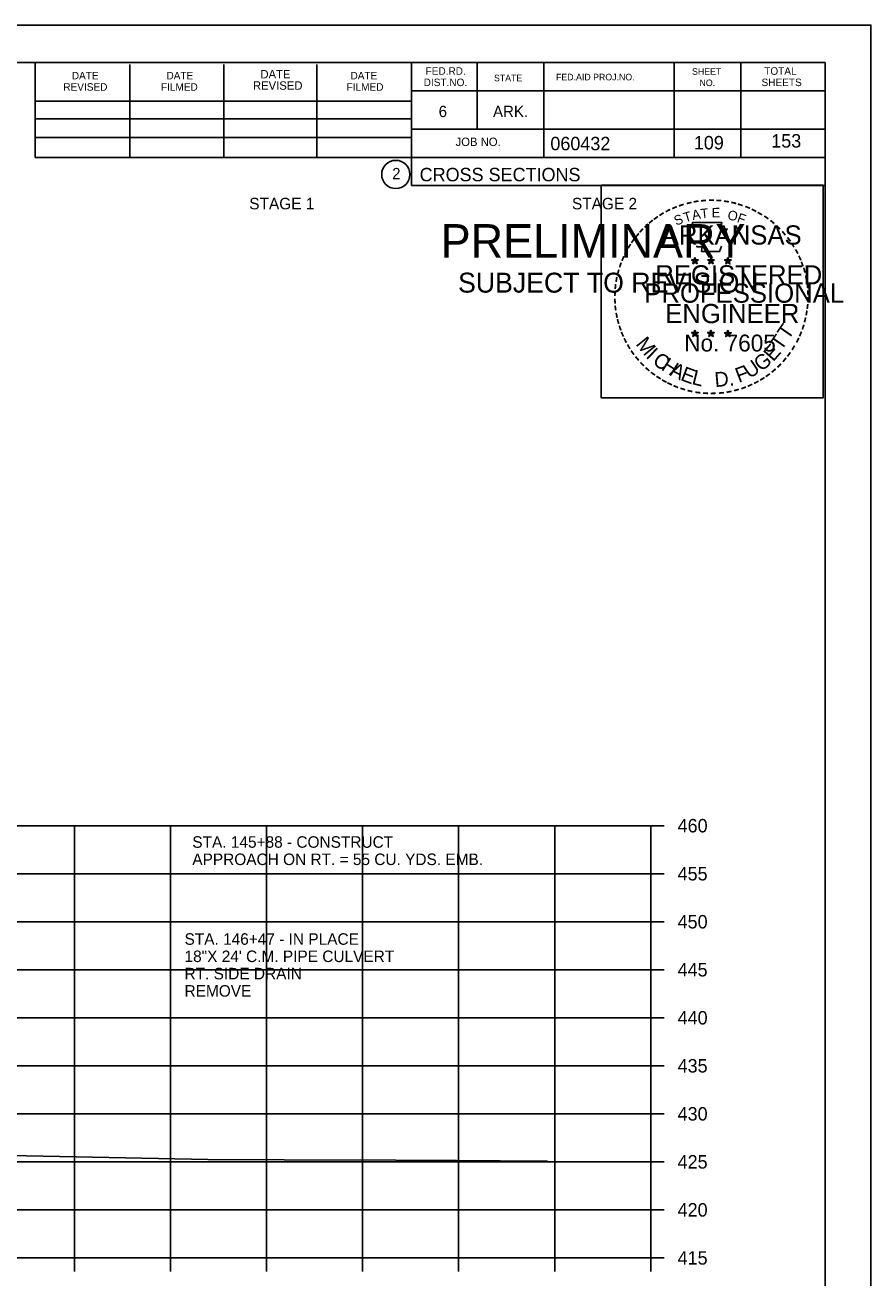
# Model space of a CAD drawing. Extents: x 1538688 to 1540766, y 656250 to 671912.
# Drawn here: x 1538933 to 1539021.1, y 663674.3 to 663804.7 of the extents above; entities that cross this region are included whole.
import ezdxf

# ---------------------------------------------------------------- set-up
doc = ezdxf.new("R2010")
doc.units = 0
for name, color, linetype in [('18', 7, 'Continuous'), ('22', 7, 'Continuous'), ('26', 7, 'Continuous'), ('7', 7, 'Continuous'), ('8', 7, 'Continuous'), ('9', 7, 'Continuous'), ('Borings', 7, 'Continuous'), ('Default', 7, 'Continuous'), ('Horizontal Alignment', 7, 'Continuous'), ('RipRap', 7, 'Continuous')]:
    doc.layers.add(name, color=color, linetype=linetype)

msp = doc.modelspace()

# ---------------------------------------------------------------- linework, layer by layer
at = {"layer": '18'}
msp.add_lwpolyline([(1538931.47, 663687.04), (1538952.08, 663686.63), (1538960, 663686.59), (1538971.63, 663686.54), (1538977.97, 663686.51), (1538987.1, 663686.44), (1538987.42, 663686.44)], dxfattribs=at)
at = {"layer": '22'}
for p, q in [((1538718.18, 663721.37), (1538998.18, 663721.37)), ((1538938.18, 663676.37), (1538938.18, 663721.37)), ((1538948.18, 663676.37), (1538948.18, 663721.37)), ((1538958.18, 663676.37), (1538958.18, 663721.37)), ((1538968.18, 663676.37), (1538968.18, 663721.37)), ((1538978.18, 663676.37), (1538978.18, 663721.37)), ((1538988.18, 663676.37), (1538988.18, 663721.37)), ((1538998.18, 663676.37), (1538998.18, 663721.37)), ((1538718.18, 663716.37), (1538998.18, 663716.37)), ((1538718.18, 663711.37), (1538998.18, 663711.37)), ((1538718.18, 663706.37), (1538998.18, 663706.37)), ((1538718.18, 663701.37), (1538998.18, 663701.37)), ((1538718.18, 663696.37), (1538998.18, 663696.37)), ((1538718.18, 663691.37), (1538998.18, 663691.37)), ((1538718.18, 663686.37), (1538998.18, 663686.37)), ((1538718.18, 663681.37), (1538998.18, 663681.37)), ((1538718.18, 663676.37), (1538998.18, 663676.37))]:
    msp.add_line(p, q, dxfattribs=at)
at = {"layer": '26'}
msp.add_line((1538687.78, 663804.73), (1539021.11, 663804.73), dxfattribs=at)
for points in [[(1538687.77, 663804.73), (1539021.11, 663804.73), (1539021.11, 663591.39), (1538687.77, 663591.39)], [(1538993.03, 663788.06), (1539016.13, 663788.06), (1539016.13, 663765.91), (1538993.03, 663765.91)]]:
    msp.add_lwpolyline(points, close=True, dxfattribs=at)
at = {"layer": '8'}
for p, q in [((1539002.44, 663780.28), (1539002.79, 663780.17)), ((1539002.44, 663780.28), (1539002.69, 663780.23)), ((1539002.44, 663780.28), (1539002.68, 663780.16)), ((1539002.57, 663779.87), (1539002.79, 663780.17)), ((1539002.57, 663779.87), (1539002.7, 663780.11)), ((1539002.57, 663779.87), (1539002.79, 663780.09)), ((1539002.79, 663780.53), (1539002.75, 663780.28)), ((1539002.79, 663780.17), (1539002.79, 663780.53)), ((1539002.79, 663780.53), (1539002.84, 663780.28)), ((1539003.13, 663780.28), (1539002.79, 663780.17)), ((1539003, 663779.87), (1539002.79, 663780.17)), ((1539003, 663779.87), (1539002.79, 663780.08)), ((1539003.13, 663780.28), (1539002.85, 663780.23)), ((1539003, 663779.87), (1539002.86, 663780.16)), ((1539003.13, 663780.28), (1539002.93, 663780.18)), ((1539004.11, 663780.28), (1539004.46, 663780.17)), ((1539004.11, 663780.28), (1539004.36, 663780.23)), ((1539004.11, 663780.28), (1539004.35, 663780.16)), ((1539004.24, 663779.87), (1539004.46, 663780.17)), ((1539004.24, 663779.87), (1539004.37, 663780.11)), ((1539004.24, 663779.87), (1539004.46, 663780.09)), ((1539004.46, 663780.53), (1539004.42, 663780.28)), ((1539004.46, 663780.17), (1539004.46, 663780.53)), ((1539004.46, 663780.53), (1539004.51, 663780.28)), ((1539004.8, 663780.28), (1539004.46, 663780.17)), ((1539004.67, 663779.87), (1539004.46, 663780.17)), ((1539004.67, 663779.87), (1539004.46, 663780.08)), ((1539004.8, 663780.28), (1539004.52, 663780.23)), ((1539004.67, 663779.87), (1539004.53, 663780.16)), ((1539004.8, 663780.28), (1539004.6, 663780.18)), ((1539005.87, 663780.27), (1539006.22, 663780.16)), ((1539005.87, 663780.27), (1539006.13, 663780.22)), ((1539005.87, 663780.27), (1539006.11, 663780.14)), ((1539006.01, 663779.86), (1539006.22, 663780.16)), ((1539006.01, 663779.86), (1539006.13, 663780.1)), ((1539006.01, 663779.86), (1539006.22, 663780.08)), ((1539006.22, 663780.52), (1539006.18, 663780.27)), ((1539006.22, 663780.16), (1539006.22, 663780.52)), ((1539006.22, 663780.52), (1539006.27, 663780.27)), ((1539006.57, 663780.27), (1539006.22, 663780.16)), ((1539006.43, 663779.86), (1539006.22, 663780.16)), ((1539006.43, 663779.86), (1539006.22, 663780.07)), ((1539006.57, 663780.27), (1539006.28, 663780.22)), ((1539006.43, 663779.86), (1539006.3, 663780.15)), ((1539006.57, 663780.27), (1539006.36, 663780.16)), ((1539002.43, 663772.71), (1539002.78, 663772.59)), ((1539002.43, 663772.71), (1539002.69, 663772.66)), ((1539002.43, 663772.71), (1539002.67, 663772.58)), ((1539002.57, 663772.3), (1539002.78, 663772.59)), ((1539002.57, 663772.3), (1539002.69, 663772.54)), ((1539002.57, 663772.3), (1539002.78, 663772.51)), ((1539002.78, 663772.96), (1539002.74, 663772.71)), ((1539002.78, 663772.59), (1539002.78, 663772.96)), ((1539002.78, 663772.96), (1539002.83, 663772.71)), ((1539003.13, 663772.71), (1539002.78, 663772.59)), ((1539003, 663772.3), (1539002.78, 663772.59)), ((1539003, 663772.3), (1539002.78, 663772.51)), ((1539003.13, 663772.71), (1539002.84, 663772.66)), ((1539003, 663772.3), (1539002.86, 663772.59)), ((1539003.13, 663772.71), (1539002.93, 663772.6)), ((1539004.1, 663772.71), (1539004.45, 663772.59)), ((1539004.1, 663772.71), (1539004.36, 663772.66)), ((1539004.1, 663772.71), (1539004.34, 663772.58)), ((1539004.24, 663772.3), (1539004.45, 663772.59)), ((1539004.24, 663772.3), (1539004.36, 663772.54)), ((1539004.24, 663772.3), (1539004.45, 663772.51)), ((1539004.45, 663772.96), (1539004.41, 663772.71)), ((1539004.45, 663772.59), (1539004.45, 663772.96)), ((1539004.45, 663772.96), (1539004.5, 663772.71)), ((1539004.8, 663772.71), (1539004.45, 663772.59)), ((1539004.67, 663772.3), (1539004.45, 663772.59)), ((1539004.67, 663772.3), (1539004.45, 663772.51)), ((1539004.8, 663772.71), (1539004.51, 663772.66)), ((1539004.67, 663772.3), (1539004.53, 663772.59)), ((1539004.8, 663772.71), (1539004.6, 663772.6)), ((1539005.87, 663772.7), (1539006.22, 663772.58)), ((1539005.87, 663772.7), (1539006.12, 663772.65)), ((1539005.87, 663772.7), (1539006.11, 663772.57)), ((1539006, 663772.29), (1539006.22, 663772.58)), ((1539006, 663772.29), (1539006.13, 663772.53)), ((1539006, 663772.29), (1539006.22, 663772.5)), ((1539006.22, 663772.95), (1539006.18, 663772.7)), ((1539006.22, 663772.58), (1539006.22, 663772.95)), ((1539006.22, 663772.95), (1539006.27, 663772.7)), ((1539006.57, 663772.7), (1539006.22, 663772.58)), ((1539006.43, 663772.29), (1539006.22, 663772.58)), ((1539006.43, 663772.29), (1539006.22, 663772.5)), ((1539006.57, 663772.7), (1539006.28, 663772.65)), ((1539006.43, 663772.29), (1539006.3, 663772.58)), ((1539006.57, 663772.7), (1539006.36, 663772.59))]:
    msp.add_line(p, q, dxfattribs=at)
for points in [[(1539002.48, 663784.16), (1539002.75, 663783.33)], [(1539005.99, 663783.23), (1539006.13, 663783.52), (1539005.45, 663783.49), (1539005.6, 663784.16), (1539002.48, 663784.16)], [(1539002.97, 663781.73), (1539002.97, 663781.65), (1539003.53, 663781.63), (1539003.48, 663781.15), (1539005.35, 663781.15), (1539005.55, 663781.69)], [(1539002.79, 663780.53), (1539003, 663779.87), (1539002.44, 663780.28), (1539003.13, 663780.28), (1539002.57, 663779.87), (1539002.79, 663780.53)], [(1539004.46, 663780.53), (1539004.67, 663779.87), (1539004.11, 663780.28), (1539004.8, 663780.28), (1539004.24, 663779.87), (1539004.46, 663780.53)], [(1539006.22, 663780.52), (1539006.43, 663779.86), (1539005.87, 663780.27), (1539006.57, 663780.27), (1539006.01, 663779.86), (1539006.22, 663780.52)], [(1539002.78, 663772.96), (1539003, 663772.3), (1539002.43, 663772.71), (1539003.13, 663772.71), (1539002.57, 663772.3), (1539002.78, 663772.96)], [(1539004.45, 663772.96), (1539004.67, 663772.3), (1539004.1, 663772.71), (1539004.8, 663772.71), (1539004.24, 663772.3), (1539004.45, 663772.96)], [(1539006.22, 663772.95), (1539006.43, 663772.29), (1539005.87, 663772.7), (1539006.57, 663772.7), (1539006, 663772.29), (1539006.22, 663772.95)]]:
    msp.add_lwpolyline(points, dxfattribs=at)
for centre, radius in [((1539002.79, 663780.17), 0.172), ((1539002.79, 663780.17), 0.145), ((1539002.79, 663780.17), 0.116), ((1539002.79, 663780.17), 0.0991), ((1539002.79, 663780.17), 0.0747), ((1539002.79, 663780.17), 0.0495), ((1539002.79, 663780.17), 0.0296), ((1539004.46, 663780.17), 0.172), ((1539004.46, 663780.17), 0.145), ((1539004.46, 663780.17), 0.116), ((1539004.46, 663780.17), 0.0991), ((1539004.46, 663780.17), 0.0747), ((1539004.46, 663780.17), 0.0495), ((1539004.46, 663780.17), 0.0296), ((1539006.22, 663780.16), 0.172), ((1539006.22, 663780.16), 0.145), ((1539006.22, 663780.16), 0.116), ((1539006.22, 663780.16), 0.0991), ((1539006.22, 663780.16), 0.0747), ((1539006.22, 663780.16), 0.0495), ((1539006.22, 663780.16), 0.0296), ((1539002.78, 663772.59), 0.172), ((1539002.78, 663772.59), 0.145), ((1539002.78, 663772.59), 0.116), ((1539002.78, 663772.59), 0.0991), ((1539002.78, 663772.59), 0.0747), ((1539002.78, 663772.59), 0.0495), ((1539002.78, 663772.59), 0.0296), ((1539004.45, 663772.59), 0.172), ((1539004.45, 663772.59), 0.145), ((1539004.45, 663772.59), 0.116), ((1539004.45, 663772.59), 0.0991), ((1539004.45, 663772.59), 0.0747), ((1539004.45, 663772.59), 0.0495), ((1539004.45, 663772.59), 0.0296), ((1539006.22, 663772.58), 0.172), ((1539006.22, 663772.58), 0.145), ((1539006.22, 663772.58), 0.116), ((1539006.22, 663772.58), 0.0991), ((1539006.22, 663772.58), 0.0747), ((1539006.22, 663772.58), 0.0495), ((1539006.22, 663772.58), 0.0296)]:
    msp.add_circle(centre, radius, dxfattribs=at)
at = {"layer": 'Borings'}
for p, q in [((1538998.18, 663676.37), (1538998.18, 663721.37)), ((1538999.58, 663721.37), (1538998.18, 663721.37)), ((1538999.58, 663716.37), (1538998.18, 663716.37)), ((1538999.58, 663711.37), (1538998.18, 663711.37)), ((1538999.58, 663706.37), (1538998.18, 663706.37)), ((1538999.58, 663701.37), (1538998.18, 663701.37)), ((1538999.58, 663696.37), (1538998.18, 663696.37)), ((1538999.58, 663691.37), (1538998.18, 663691.37)), ((1538999.58, 663686.37), (1538998.18, 663686.37)), ((1538999.58, 663681.37), (1538998.18, 663681.37)), ((1538718.18, 663676.37), (1538998.18, 663676.37)), ((1538938.18, 663674.97), (1538938.18, 663676.37)), ((1538948.18, 663674.97), (1538948.18, 663676.37)), ((1538958.18, 663674.97), (1538958.18, 663676.37)), ((1538968.18, 663674.97), (1538968.18, 663676.37)), ((1538978.18, 663674.97), (1538978.18, 663676.37)), ((1538988.18, 663674.97), (1538988.18, 663676.37)), ((1538998.18, 663674.97), (1538998.18, 663676.37)), ((1538999.58, 663676.37), (1538998.18, 663676.37))]:
    msp.add_line(p, q, dxfattribs=at)
at = {"layer": 'RipRap'}
for p, q in [((1538700.18, 663800.83), (1539016.36, 663800.83)), ((1538934.1, 663790.95), (1538934.1, 663800.83)), ((1538973.26, 663800.83), (1538973.26, 663788.03)), ((1538980.1, 663800.83), (1538980.1, 663793.89)), ((1538987.04, 663800.83), (1538987.04, 663790.95)), ((1539000.62, 663800.83), (1539000.62, 663790.95)), ((1539007.56, 663800.83), (1539007.56, 663790.95)), ((1539016.36, 663595.37), (1539016.36, 663800.83)), ((1538943.96, 663790.95), (1538943.96, 663800.63)), ((1538953.72, 663790.95), (1538953.72, 663800.63)), ((1538963.4, 663790.95), (1538963.4, 663800.63)), ((1538934.1, 663796.81), (1538973.26, 663796.81)), ((1539016.36, 663797.89), (1538973.26, 663797.89)), ((1539016.36, 663797.91), (1539016.36, 663797.91)), ((1538934.1, 663794.95), (1538973.26, 663794.95)), ((1538934.1, 663790.95), (1538934.1, 663793.01)), ((1538934.1, 663793.01), (1538973.26, 663793.01)), ((1539016.36, 663793.89), (1538973.26, 663793.89)), ((1538976.22, 663793.89), (1539016.36, 663793.89)), ((1539016.36, 663790.95), (1538934.1, 663790.95)), ((1538973.26, 663788.03), (1539016.36, 663788.03))]:
    msp.add_line(p, q, dxfattribs=at)
msp.add_circle((1538971.64, 663789.17), 1.47, dxfattribs=at)

# ---------------------------------------------------------------- texts
at = {"layer": '7'}
for s, height, p in [('109', 1.4, (1539002.67, 663791.78)), ('153', 1.4, (1539010.73, 663791.97)), ('STA. 145+88 - CONSTRUCT', 1.2, (1538950.45, 663719.07)), ('APPROACH ON RT. = 55 CU. YDS. EMB.', 1.2, (1538950.45, 663717.27))]:
    msp.add_text(s, height=height, dxfattribs=at).set_placement(p)
at = {"layer": '8'}
for s, height, rotation, p in [('-', 1.6, 13.6301, (1539001.98, 663785.52)), ('-', 1.6, 10.2193, (1539002.66, 663785.69)), ('-', 1.6, 5.8968, (1539003.38, 663785.8)), ('-', 1.6, 0.1862, (1539004.16, 663785.87)), ('-', 1.6, 357.743, (1539004.88, 663785.86)), ('-', 1.6, 352.1617, (1539005.62, 663785.8)), ('-', 1.6, 347.2049, (1539006.34, 663785.69)), ('-', 1.6, 34.0636, (1538999.36, 663784.33)), ('-', 1.6, 28.7918, (1538999.96, 663784.7)), ('-', 1.6, 24.3072, (1539000.59, 663785.01)), ('-', 1.6, 19.1761, (1539001.23, 663785.28)), ('T', 1, 16.4036, (1539001.75, 663784.17)), ('A', 1, 11.2132, (1539002.57, 663784.42)), ('T', 1, 6.0228, (1539003.42, 663784.58)), ('E', 1, 0.8323, (1539004.53, 663784.69)), ('O', 1, 350.4515, (1539006.13, 663784.48)), ('F', 1, 340.0707, (1539007.09, 663784.25)), ('-', 1.6, 342.3362, (1539006.98, 663785.53)), ('-', 1.6, 337.8551, (1539007.71, 663785.31)), ('-', 1.6, 334.1211, (1539008.34, 663785.04)), ('-', 1.6, 329.6409, (1539008.92, 663784.75)), ('-', 1.6, 42.9622, (1538997.88, 663783.14)), ('-', 1.6, 38.9507, (1538998.31, 663783.55)), ('-', 1.6, 36.2317, (1538998.79, 663783.93)), ('ARKANSAS', 2, 360, (1538999.33, 663781.87)), ('S', 1, 21.594, (1539000.83, 663783.83)), ('-', 1.6, 325.8627, (1539009.57, 663784.39)), ('-', 1.6, 320.5297, (1539010.18, 663783.97)), ('-', 1.6, 315.5786, (1539010.77, 663783.48)), ('-', 1.6, 54.2325, (1538996.61, 663781.61)), ('-', 1.6, 50.6142, (1538997.03, 663782.17)), ('-', 1.6, 48.423, (1538997.43, 663782.66)), ('-', 1.6, 309.8797, (1539011.34, 663782.93)), ('-', 1.6, 306.6522, (1539011.87, 663782.33)), ('-', 1.6, 62.8713, (1538995.97, 663780.47)), ('-', 1.6, 58.0706, (1538996.29, 663781.08)), ('-', 1.4, 303.6753, (1539012.35, 663781.76)), ('-', 1.6, 299.6684, (1539012.67, 663781.15)), ('-', 1.6, 72.3945, (1538995.5, 663779.22)), ('-', 1.6, 67.7743, (1538995.72, 663779.85)), ('DWB', 0.01, 360, (1539002.77, 663780.16)), ('DWB', 0.01, 360, (1539004.44, 663780.16)), ('DWB', 0.01, 360, (1539006.21, 663780.15)), ('-', 1.6, 294.6628, (1539013, 663780.54)), ('-', 1.6, 290.5728, (1539013.25, 663779.96)), ('-', 1.6, 81.2013, (1538995.17, 663777.8)), ('-', 1.6, 75.461, (1538995.3, 663778.51)), ('REGISTERED', 2, 360, (1538998.65, 663777.72)), ('-', 1.6, 285.1233, (1539013.49, 663779.38)), ('-', 1.6, 280.5493, (1539013.69, 663778.64)), ('-', 1.6, 85.1863, (1538995.09, 663777.11)), ('PROFESSIONAL', 2, 360, (1538997.51, 663775.82)), ('-', 1.6, 276.5962, (1539013.85, 663777.87)), ('-', 1.6, 94.1959, (1538995.1, 663775.68)), ('-', 1.6, 89.0622, (1538995.07, 663776.41)), ('-', 1.6, 274.3301, (1539013.91, 663777.15)), ('-', 1.6, 269.9407, (1539013.94, 663776.52)), ('-', 1.6, 98.9479, (1538995.17, 663775.01)), ('-', 1.6, 101.7149, (1538995.31, 663774.28)), ('ENGINEER', 2, 360, (1538999.69, 663773.69)), ('-', 1.6, 260.9953, (1539013.85, 663775.2)), ('-', 1.6, 263.5172, (1539013.93, 663775.85)), ('-', 1.6, 105.4578, (1538995.47, 663773.69)), ('-', 1.6, 109.0874, (1538995.69, 663773.05)), ('T', 1.54, 55.055, (1539012.5, 663771.86)), ('-', 1.6, 252.8681, (1539013.56, 663773.8)), ('-', 1.6, 255.7626, (1539013.74, 663774.52)), ('-', 1.6, 114.0643, (1538995.94, 663772.46)), ('-', 1.6, 115.7289, (1538996.24, 663771.84)), ('M', 1.54, 308.9175, (1538996.55, 663771.49)), ('No. 7605', 1.757, 360, (1539001.67, 663770.74)), ('DWB', 0.01, 360, (1539002.77, 663772.59)), ('DWB', 0.01, 360, (1539004.44, 663772.59)), ('DWB', 0.01, 360, (1539006.2, 663772.58)), ('T', 1.54, 55.055, (1539011.77, 663770.74)), ('-', 1.6, 244.6197, (1539013.08, 663772.5)), ('-', 1.6, 247.8887, (1539013.34, 663773.13)), ('-', 1.6, 120.4471, (1538996.6, 663771.25)), ('-', 1.6, 125.8934, (1538997, 663770.69)), ('I', 1.54, 316.4636, (1538997.6, 663770.17)), ('E', 1.54, 48.7313, (1539010.93, 663769.61)), ('-', 1.6, 233.8452, (1539012.28, 663771.09)), ('-', 1.6, 239.0712, (1539012.68, 663771.75)), ('-', 1.6, 130.7181, (1538997.47, 663770.14)), ('-', 1.6, 134.2238, (1538997.98, 663769.6)), ('C', 1.54, 324.0197, (1538998.27, 663769.54)), ('H', 1.54, 327.5342, (1538999.18, 663768.89)), ('A', 1.54, 332.5513, (1539000.03, 663768.35)), ('U', 1.54, 34.4052, (1539008.47, 663767.86)), ('G', 1.54, 38.2173, (1539009.67, 663768.59)), ('-', 1.6, 225.7653, (1539011.37, 663769.96)), ('-', 1.6, 231.2538, (1539011.85, 663770.53)), ('-', 1.6, 138.9338, (1538998.51, 663769.13)), ('-', 1.6, 144.6463, (1538999.06, 663768.73)), ('-', 1.6, 148.0898, (1538999.63, 663768.36)), ('E', 1.54, 339.2068, (1539001.19, 663767.79)), ('L', 1.54, 346.2929, (1539002.38, 663767.36)), ('D.', 1.54, 5.2602, (1539004.89, 663767.03)), ('F', 1.54, 20.8202, (1539007.34, 663767.47)), ('-', 1.6, 212.2491, (1539009.77, 663768.6)), ('-', 1.6, 215.7363, (1539010.3, 663768.98)), ('-', 1.6, 221.0851, (1539010.85, 663769.45)), ('-', 1.6, 151.5704, (1539000.2, 663768.03)), ('-', 1.6, 154.6002, (1539000.73, 663767.78)), ('-', 1.6, 158.5612, (1539001.35, 663767.53)), ('-', 1.6, 162.7983, (1539002.04, 663767.32)), ('-', 1.6, 167.5555, (1539002.75, 663767.15)), ('-', 1.6, 195.4743, (1539007.29, 663767.42)), ('-', 1.6, 200.7184, (1539007.97, 663767.66)), ('-', 1.6, 204.2516, (1539008.59, 663767.93)), ('-', 1.6, 207.3568, (1539009.21, 663768.25)), ('-', 1.6, 173.1155, (1539003.52, 663767.04)), ('-', 1.6, 176.5183, (1539004.27, 663766.99)), ('-', 1.6, 181.5918, (1539005.02, 663767.01)), ('-', 1.6, 185.8167, (1539005.83, 663767.08)), ('-', 1.6, 191.2858, (1539006.56, 663767.22))]:
    msp.add_text(s, height=height, rotation=rotation, dxfattribs=at).set_placement(p)
at = {"layer": '9'}
for s, height, p in [('PRELIMINARY', 3.5, (1538976.31, 663780.5)), ('DWB', 0.01, (1538977.06, 663782.34)), ('SUBJECT TO REVISION', 2.0751, (1538978.12, 663776.87))]:
    msp.add_text(s, height=height, rotation=360, dxfattribs=at).set_placement(p)
at = {"layer": 'Default'}
for s, p in [('STAGE 1', (1538956.38, 663785.54)), ('STAGE 2', (1538989.98, 663785.54)), ('STA. 146+47 - IN PLACE', (1538949.64, 663708.97)), ('18"X 24\' C.M. PIPE CULVERT', (1538949.64, 663707.17)), ('RT. SIDE DRAIN', (1538949.64, 663705.37)), ('REMOVE', (1538949.64, 663703.57))]:
    msp.add_text(s, height=1.2, dxfattribs=at).set_placement(p)
at = {"layer": 'Horizontal Alignment'}
for s, p in [('460', (1539000.98, 663720.67)), ('455', (1539000.98, 663715.67)), ('450', (1539000.98, 663710.67)), ('445', (1539000.98, 663705.67)), ('440', (1539000.98, 663700.67)), ('435', (1539000.98, 663695.67)), ('430', (1539000.98, 663690.67)), ('425', (1539000.98, 663685.67)), ('420', (1539000.98, 663680.67)), ('415', (1539000.98, 663675.67))]:
    msp.add_text(s, height=1.4, dxfattribs=at).set_placement(p)
at = {"layer": 'RipRap'}
for s, height, p in [('DATE', 0.782, (1538937.9, 663799.07)), ('DATE', 0.782, (1538947.76, 663799.07)), ('DATE', 0.879, (1538957.54, 663799.17)), ('DATE', 0.782, (1538966.92, 663799.07)), ('FED.RD.', 0.782, (1538974.74, 663799.55)), ('STATE', 0.684, (1538981.86, 663798.87)), ('FED.AID PROJ.NO.', 0.684, (1538988.32, 663798.97)), ('SHEET', 0.684, (1539002.48, 663799.55)), ('TOTAL', 0.782, (1539010, 663799.55)), ('REVISED', 0.782, (1538937.02, 663797.89)), ('FILMED', 0.782, (1538947.18, 663797.89)), ('REVISED', 0.879, (1538956.76, 663797.99)), ('FILMED', 0.782, (1538966.52, 663797.89)), ('DIST.NO.', 0.782, (1538974.54, 663798.37)), ('NO.', 0.684, (1539003.26, 663798.37)), ('SHEETS', 0.782, (1539009.72, 663798.37)), ('6', 1.17, (1538976.1, 663795.15)), ('ARK.', 1.172, (1538981.76, 663795.15)), ('JOB NO.', 0.879, (1538977.86, 663792.13)), ('060432', 1.4, (1538987.73, 663791.69)), ('2', 1.17, (1538971.26, 663788.68)), ('CROSS SECTIONS', 1.4, (1538974.12, 663788.46))]:
    msp.add_text(s, height=height, rotation=360, dxfattribs=at).set_placement(p)

doc.saveas('drawing.dxf')
